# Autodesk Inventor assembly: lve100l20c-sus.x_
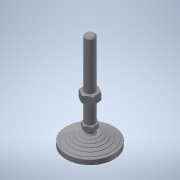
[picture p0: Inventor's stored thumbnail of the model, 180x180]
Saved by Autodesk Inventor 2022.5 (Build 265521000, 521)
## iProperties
Part Number: lve100l20c-sus.x_
Material: 一般
Document SubType Name: Assembly
Designer: ImaoCorp
Sending System: SOLIDWORKS 2017-2017317
MC: AMD64
MC_MODEL: Intel64 Family 6 Model 60 Stepping 3, GenuineIntel
OS: Windows_NT
FRU: Parasolid Version 29.0, build 201,  4-17-2017
FORMAT: text
GUISE: transmit
KEY: lve100l20c-sus
FILE: lve100l20c-sus.x_t
DATE: Mon Jul 01 18:16:50 2019
Author: ImaoCorp
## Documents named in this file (3)
- X:\14_SW2022-Inv2022\00_全2023-1023新製品(TCC)まで\l\lve100l20c-sus\LVE100L20C-SUS.iam
- X:\14_SW2022-Inv2022\00_全2023-1023新製品(TCC)まで\l\lve100l20c-sus\lve100l20c-sus_01.ipt
- X:\14_SW2022-Inv2022\00_全2023-1023新製品(TCC)まで\l\lve100l20c-sus\lve100l20c-sus_02.ipt
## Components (2 placed, 2 different names)
1. lve100l20c-sus_01
2. lve100l20c-sus_02
